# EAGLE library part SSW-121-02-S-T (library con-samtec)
THROUGH-HOLE .025" SQ POST SOCKET Source: Samtec SSW.pdf
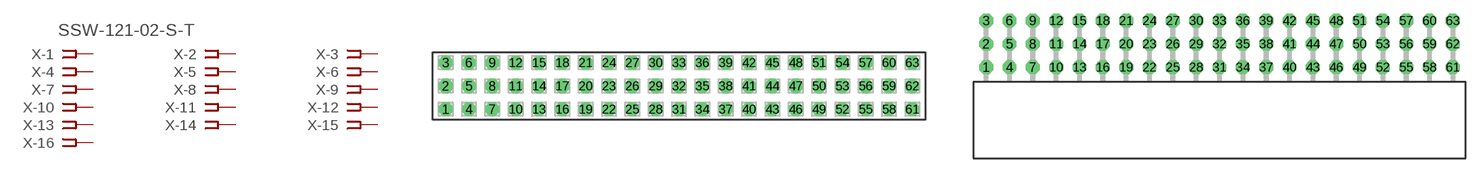
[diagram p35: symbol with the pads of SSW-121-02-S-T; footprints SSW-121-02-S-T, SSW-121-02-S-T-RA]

Designator prefix X; gates -1=FPINV -2=FPIN -3=FPIN -4=FPIN -5=FPIN -6=FPIN -7=FPIN -8=FPIN -9=FPIN -10=FPIN -11=FPIN -12=FPIN -13=FPIN -14=FPIN -15=FPIN -16=FPIN -17=FPIN -18=FPIN -19=FPIN -20=FPIN -21=FPIN -22=FPIN -23=FPIN -24=FPIN -25=FPIN -26=FPIN -27=FPIN -28=FPIN -29=FPIN -30=FPIN -31=FPIN -32=FPIN -33=FPIN -34=FPIN -35=FPIN -36=FPIN -37=FPIN -38=FPIN -39=FPIN -40=FPIN -41=FPIN -42=FPIN -43=FPIN -44=FPIN -45=FPIN -46=FPIN -47=FPIN -48=FPIN -49=FPIN -50=FPIN -51=FPIN -52=FPIN -53=FPIN -54=FPIN -55=FPIN -56=FPIN -57=FPIN -58=FPIN -59=FPIN -60=FPIN -61=FPIN -62=FPIN -63=FPIN

## SSW-121-02-S-T (OC_FARNELL: unknown; OC_NEWARK: unknown)  [SSW-121-02-S-T]
1  -1:1  pas
2  -2:1  pas
3  -3:1  pas
4  -4:1  pas
5  -5:1  pas
6  -6:1  pas
7  -7:1  pas
8  -8:1  pas
9  -9:1  pas
10  -10:1  pas
11  -11:1  pas
12  -12:1  pas
13  -13:1  pas
14  -14:1  pas
15  -15:1  pas
16  -16:1  pas
17  -17:1  pas
18  -18:1  pas
19  -19:1  pas
20  -20:1  pas
21  -21:1  pas
22  -22:1  pas
23  -23:1  pas
24  -24:1  pas
25  -25:1  pas
26  -26:1  pas
27  -27:1  pas
28  -28:1  pas
29  -29:1  pas
30  -30:1  pas
31  -31:1  pas
32  -32:1  pas
33  -33:1  pas
34  -34:1  pas
35  -35:1  pas
36  -36:1  pas
37  -37:1  pas
38  -38:1  pas
39  -39:1  pas
40  -40:1  pas
41  -41:1  pas
42  -42:1  pas
43  -43:1  pas
44  -44:1  pas
45  -45:1  pas
46  -46:1  pas
47  -47:1  pas
48  -48:1  pas
49  -49:1  pas
50  -50:1  pas
51  -51:1  pas
52  -52:1  pas
53  -53:1  pas
54  -54:1  pas
55  -55:1  pas
56  -56:1  pas
57  -57:1  pas
58  -58:1  pas
59  -59:1  pas
60  -60:1  pas
61  -61:1  pas
62  -62:1  pas
63  -63:1  pas

## SSW-121-02-S-TRA (MPN: SSW-121-02-S-T-RA; OC_FARNELL: unknown; OC_NEWARK: 82P8645)  [SSW-121-02-S-T-RA]
Pads as for SSW-121-02-S-T

## Footprint SSW-121-02-S-T (pad centres in mm)
THROUGH-HOLE .025" SQ POST SOCKET Source: Samtec SSW.pdf
drill 1 pad 1.5 octagon: 1 -25.4,-2.54; 2 -25.4,0; 3 -25.4,2.54; 4 -22.86,-2.54; 5 -22.86,0; 6 -22.86,2.54; 7 -20.32,-2.54; 8 -20.32,0; 9 -20.32,2.54; 10 -17.78,-2.54; 11 -17.78,0; 12 -17.78,2.54; 13 -15.24,-2.54; 14 -15.24,0; 15 -15.24,2.54; 16 -12.7,-2.54; 17 -12.7,0; 18 -12.7,2.54; 19 -10.16,-2.54; 20 -10.16,0; 21 -10.16,2.54; 22 -7.62,-2.54; 23 -7.62,0; 24 -7.62,2.54; 25 -5.08,-2.54; 26 -5.08,0; 27 -5.08,2.54; 28 -2.54,-2.54; 29 -2.54,0; 30 -2.54,2.54; 31 0,-2.54; 32 0,0; 33 0,2.54; 34 2.54,-2.54; 35 2.54,0; 36 2.54,2.54; 37 5.08,-2.54; 38 5.08,0; 39 5.08,2.54; 40 7.62,-2.54; 41 7.62,0; 42 7.62,2.54; 43 10.16,-2.54; 44 10.16,0; 45 10.16,2.54; 46 12.7,-2.54; 47 12.7,0; 48 12.7,2.54; 49 15.24,-2.54; 50 15.24,0; 51 15.24,2.54; 52 17.78,-2.54; 53 17.78,0; 54 17.78,2.54; 55 20.32,-2.54; 56 20.32,0; 57 20.32,2.54; 58 22.86,-2.54; 59 22.86,0; 60 22.86,2.54; 61 25.4,-2.54; 62 25.4,0; 63 25.4,2.54

## Footprint SSW-121-02-S-T-RA (pad centres in mm)
THROUGH-HOLE .025" SQ POST SOCKET Source: Samtec SSW.pdf
drill 1 pad 1.5 octagon: 1 -25.4,1.524; 2 -25.4,4.064; 3 -25.4,6.604; 4 -22.86,1.524; 5 -22.86,4.064; 6 -22.86,6.604; 7 -20.32,1.524; 8 -20.32,4.064; 9 -20.32,6.604; 10 -17.78,1.524; 11 -17.78,4.064; 12 -17.78,6.604; 13 -15.24,1.524; 14 -15.24,4.064; 15 -15.24,6.604; 16 -12.7,1.524; 17 -12.7,4.064; 18 -12.7,6.604; 19 -10.16,1.524; 20 -10.16,4.064; 21 -10.16,6.604; 22 -7.62,1.524; 23 -7.62,4.064; 24 -7.62,6.604; 25 -5.08,1.524; 26 -5.08,4.064; 27 -5.08,6.604; 28 -2.54,1.524; 29 -2.54,4.064; 30 -2.54,6.604; 31 0,1.524; 32 0,4.064; 33 0,6.604; 34 2.54,1.524; 35 2.54,4.064; 36 2.54,6.604; 37 5.08,1.524; 38 5.08,4.064; 39 5.08,6.604; 40 7.62,1.524; 41 7.62,4.064; 42 7.62,6.604; 43 10.16,1.524; 44 10.16,4.064; 45 10.16,6.604; 46 12.7,1.524; 47 12.7,4.064; 48 12.7,6.604; 49 15.24,1.524; 50 15.24,4.064; 51 15.24,6.604; 52 17.78,1.524; 53 17.78,4.064; 54 17.78,6.604; 55 20.32,1.524; 56 20.32,4.064; 57 20.32,6.604; 58 22.86,1.524; 59 22.86,4.064; 60 22.86,6.604; 61 25.4,1.524; 62 25.4,4.064; 63 25.4,6.604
